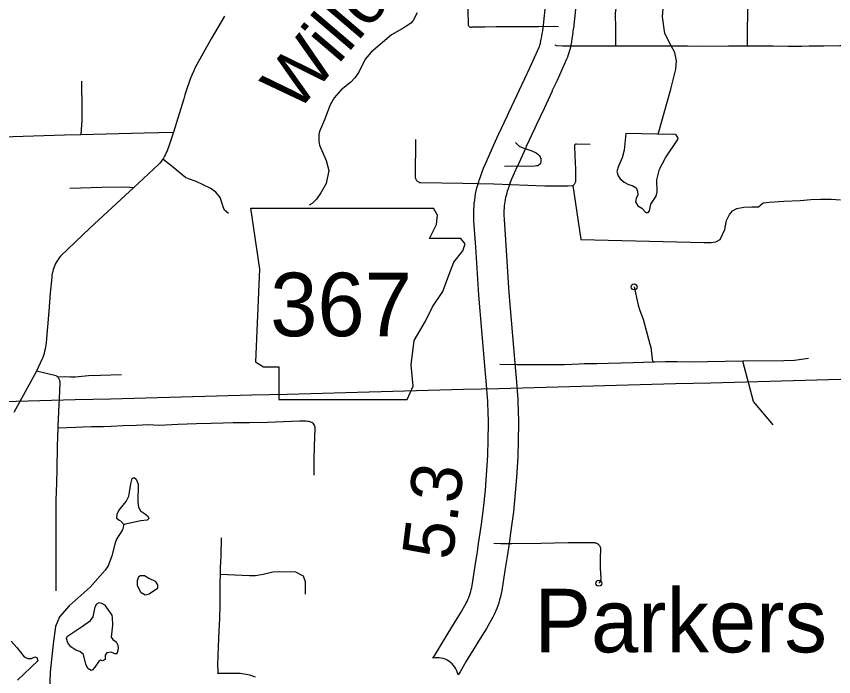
# Model space of a CAD drawing. Extents: x -19 to 366, y -4 to 359.
# Drawn here: x 152.307 to 153.594, y 182.486 to 183.524 of the extents above; entities that cross this region are included whole.
import ezdxf

# ---------------------------------------------------------------- set-up
doc = ezdxf.new("R2010")
doc.units = 0
for name, color, linetype in [('Level 10', 7, 'Continuous'), ('Level 21', 7, 'Continuous'), ('Level 24', 7, 'Continuous'), ('Level 31', 7, 'Continuous'), ('Level 32', 7, 'Continuous'), ('Level 35', 7, 'Continuous'), ('Level 48', 7, 'Continuous'), ('Level 60', 7, 'Continuous')]:
    doc.layers.add(name, color=color, linetype=linetype)

msp = doc.modelspace()

# ---------------------------------------------------------------- linework, layer by layer
at = {"layer": 'Level 10'}
for p, q in [((153.1844, 183.5056), (153.1843, 183.5052)), ((153.1792, 183.4741), (153.1791, 183.4735)), ((153.1507, 183.4066), (153.1508, 183.4067)), ((153.1235, 183.3485), (153.1236, 183.3485)), ((153.1093, 183.3177), (153.1093, 183.3177)), ((153.0504, 183.3025), (153.0499, 183.3015)), ((153.0937, 183.2834), (153.0933, 183.2825)), ((153.0817, 183.2533), (153.0816, 183.253)), ((153.0921, 182.9788), (153.0921, 182.9788)), ((153.0827, 182.6914), (153.0826, 182.6912))]:
    msp.add_line(p, q, dxfattribs=at)
for points in [[(153.1373, 183.5104), (153.1415, 183.5515), (153.1426, 183.5598), (153.1437, 183.5679), (153.145, 183.576), (153.1514, 183.6125), (153.1599, 183.6541), (153.1603, 183.6563)], [(153.2069, 183.6477), (153.2064, 183.645), (153.1979, 183.6037), (153.1917, 183.5682), (153.1905, 183.5609), (153.1895, 183.5535), (153.1886, 183.5462), (153.1844, 183.5056)], [(153.1329, 183.4839), (153.1338, 183.4885), (153.1347, 183.4929), (153.1355, 183.4973), (153.1361, 183.5018), (153.1368, 183.5062), (153.1373, 183.5109)], [(153.1843, 183.5052), (153.1837, 183.5001), (153.183, 183.4948), (153.1822, 183.4896), (153.1812, 183.4843), (153.1802, 183.4791), (153.1792, 183.4741)], [(153.1079, 183.4268), (153.1157, 183.4433), (153.1303, 183.4758), (153.1309, 183.4773), (153.1315, 183.4789), (153.132, 183.4807), (153.1325, 183.4823), (153.133, 183.4845)], [(153.1791, 183.4735), (153.1783, 183.4705), (153.1774, 183.4671), (153.1764, 183.4639), (153.1752, 183.4605), (153.1738, 183.4572), (153.1587, 183.4235), (153.1507, 183.4066)], [(153.0806, 183.3685), (153.0829, 183.3734), (153.0953, 183.3997), (153.1079, 183.4267)], [(153.1508, 183.4067), (153.1382, 183.3796), (153.1258, 183.3533), (153.1235, 183.3485)], [(153.0662, 183.3373), (153.0671, 183.3394), (153.0806, 183.3685)], [(153.1236, 183.3485), (153.1101, 183.3196), (153.1093, 183.3177)], [(153.0499, 183.3015), (153.0502, 183.3021), (153.0552, 183.3131), (153.0662, 183.3373)], [(153.1093, 183.3177), (153.0983, 183.2935), (153.0936, 183.2833), (153.0937, 183.2834)], [(153.0367, 183.2679), (153.0386, 183.2737), (153.0407, 183.2797), (153.043, 183.2856), (153.0454, 183.2914), (153.0479, 183.2972), (153.0504, 183.3025)], [(153.0933, 183.2825), (153.091, 183.2777), (153.089, 183.273), (153.087, 183.2681), (153.0851, 183.2633), (153.0834, 183.2584), (153.0817, 183.2533)], [(153.0449, 182.9748), (153.0356, 183.0859), (153.0308, 183.1611), (153.0279, 183.2027), (153.0277, 183.2114), (153.0277, 183.2161), (153.0278, 183.221), (153.028, 183.2258), (153.0284, 183.2306), (153.029, 183.2355), (153.0297, 183.2403), (153.0305, 183.2451), (153.0315, 183.2498), (153.0326, 183.2546), (153.0339, 183.2593), (153.0354, 183.264), (153.0368, 183.2682)], [(153.0816, 183.253), (153.0804, 183.2494), (153.0794, 183.2461), (153.0785, 183.2428), (153.0777, 183.2396), (153.077, 183.2362), (153.0764, 183.2328), (153.0759, 183.2294), (153.0755, 183.2261), (153.0753, 183.2226), (153.0751, 183.2192), (153.075, 183.2159), (153.0751, 183.2122), (153.0752, 183.2048), (153.0781, 183.1643), (153.0828, 183.0894), (153.0921, 182.9788)], [(153.0358, 182.6982), (153.0398, 182.7253), (153.0429, 182.7501), (153.0458, 182.7791), (153.0477, 182.8024), (153.0495, 182.8336), (153.0503, 182.8584), (153.0507, 182.8831), (153.0502, 182.9059), (153.0499, 182.9122), (153.0496, 182.9187), (153.0492, 182.9251), (153.0487, 182.9315), (153.0482, 182.938), (153.0475, 182.9447), (153.0449, 182.9747)], [(153.0921, 182.9788), (153.0947, 182.949), (153.0953, 182.9423), (153.0959, 182.9354), (153.0965, 182.9284), (153.0969, 182.9214), (153.0972, 182.9144), (153.0975, 182.9073), (153.098, 182.8832), (153.0976, 182.8573), (153.0968, 182.8315), (153.0949, 182.7991), (153.093, 182.7749), (153.09, 182.7448), (153.0867, 182.7189), (153.0827, 182.6914)], [(152.9632, 182.5144), (152.9659, 182.5185), (152.9754, 182.5342), (152.9874, 182.5537), (152.9974, 182.5703), (153.0067, 182.5855), (153.0156, 182.6012), (153.017, 182.6039), (153.0183, 182.6068), (153.0196, 182.6099), (153.0207, 182.613), (153.0218, 182.6161), (153.0227, 182.6193), (153.0236, 182.6226), (153.0243, 182.6256), (153.0249, 182.6288), (153.0297, 182.6601), (153.0333, 182.6822), (153.0358, 182.6985)], [(153.0826, 182.6912), (153.0801, 182.6748), (153.0765, 182.6527), (153.0716, 182.6208), (153.0707, 182.6161), (153.0696, 182.6111), (153.0683, 182.6065), (153.0669, 182.6018), (153.0653, 182.5971), (153.0637, 182.5927), (153.0618, 182.588), (153.0597, 182.5835), (153.0574, 182.5789), (153.0476, 182.5615), (153.0379, 182.5456), (153.0278, 182.529), (153.0158, 182.5096), (153.006, 182.4933), (153.0028, 182.4885)]]:
    msp.add_lwpolyline(points, dxfattribs=at)
msp.add_arc((152.9702, 182.4818), 0.0334, 11.6032, 102.0217, dxfattribs=at)
at = {"layer": 'Level 21'}
for p, q in [((152.6758, 183.2228), (152.6902, 183.1267)), ((152.9706, 183.2116), (152.9639, 183.2227)), ((152.969, 183.1972), (152.9706, 183.2116)), ((152.9578, 183.1747), (152.969, 183.1972)), ((153.0074, 183.1747), (152.9578, 183.1747)), ((153.0138, 183.1667), (153.0074, 183.1747)), ((153.0106, 183.1555), (153.0138, 183.1667)), ((152.9962, 183.1379), (153.0106, 183.1555)), ((152.6902, 183.1267), (152.6838, 182.9809)), ((152.9882, 183.1171), (152.9962, 183.1379)), ((152.9786, 183.0914), (152.9882, 183.1171)), ((152.9626, 183.0674), (152.9786, 183.0914)), ((152.9514, 183.045), (152.9626, 183.0674)), ((152.9337, 183.0145), (152.9514, 183.045)), ((152.9289, 182.9761), (152.9337, 183.0145)), ((152.6838, 182.9809), (152.6966, 182.9729)), ((152.6966, 182.9729), (152.7207, 182.9729)), ((152.7207, 182.9729), (152.7207, 182.9216)), ((152.9321, 182.9424), (152.9289, 182.9761)), ((152.9225, 182.9216), (152.9321, 182.9424)), ((152.7207, 182.9216), (152.9225, 182.9216))]:
    msp.add_line(p, q, dxfattribs=at)
msp.add_lwpolyline([(152.6758, 183.2228), (152.9639, 183.2227)], dxfattribs=at)
at = {"layer": 'Level 31'}
msp.add_line((153.4585, 183.4775), (153.4594, 183.6425), dxfattribs=at)
for points in [[(153.2673, 183.6398), (153.2537, 183.5558), (153.2504, 183.5296), (153.2509, 183.5042), (153.2509, 183.4775)], [(153.1608, 183.508), (153.1551, 183.5084), (153.1294, 183.5078), (153.1112, 183.5081), (153.1016, 183.5079), (153.0628, 183.5079), (153.0448, 183.5073), (153.0243, 183.5073), (153.0235, 183.5072), (153.0228, 183.5072), (153.0221, 183.5074), (153.0214, 183.5077), (153.0208, 183.5081), (153.0202, 183.5086), (153.0198, 183.5092), (153.0195, 183.5099), (153.0193, 183.5106), (153.0192, 183.5113), (153.019, 183.5343), (153.0189, 183.5679)], [(152.6352, 183.5248), (152.6139, 183.4893), (152.5886, 183.4438), (152.586, 183.4378), (152.5834, 183.4318), (152.581, 183.4258), (152.5787, 183.4196), (152.5766, 183.4135), (152.5745, 183.4073), (152.5726, 183.401), (152.5708, 183.3947), (152.5546, 183.342)], [(153.2509, 183.4775), (153.2301, 183.4775), (153.1914, 183.4776), (153.1671, 183.4778), (153.1579, 183.4781), (153.156, 183.479)], [(153.4567, 183.4775), (153.4482, 183.4774), (153.4286, 183.4774), (153.3865, 183.4773), (153.3643, 183.4774), (153.3358, 183.4777), (153.3225, 183.4776), (153.2509, 183.4775)], [(153.4585, 183.4775), (153.4567, 183.4775)], [(153.6393, 183.4783), (153.6235, 183.478), (153.6038, 183.478), (153.5788, 183.4777), (153.5557, 183.4775), (153.5442, 183.4773), (153.5225, 183.4773), (153.4992, 183.4775), (153.476, 183.4774), (153.4593, 183.4775), (153.4585, 183.4775)], [(152.4097, 183.4225), (152.4097, 183.4152), (152.4106, 183.3853), (152.4102, 183.361), (152.4088, 183.3388)], [(152.128, 183.335), (152.1293, 183.3343), (152.1307, 183.3337), (152.1321, 183.3332), (152.1335, 183.3328), (152.135, 183.3325), (152.1364, 183.3323), (152.1379, 183.3322), (152.1394, 183.3322), (152.1409, 183.3324), (152.1614, 183.3328), (152.1884, 183.3333), (152.2111, 183.3338), (152.2283, 183.3335), (152.302, 183.3356), (152.3833, 183.3381), (152.4088, 183.3388)], [(152.4088, 183.3388), (152.5087, 183.3412), (152.5546, 183.342)], [(152.5546, 183.342), (152.5468, 183.3189), (152.5458, 183.3159), (152.5446, 183.3129), (152.5433, 183.31), (152.5419, 183.3071), (152.5404, 183.3043), (152.5388, 183.3015), (152.5377, 183.2997)], [(153.0592, 183.2606), (153.0106, 183.2617), (152.9438, 183.2625), (152.9428, 183.2627), (152.9419, 183.263), (152.941, 183.2634), (152.9401, 183.2639), (152.9393, 183.2645), (152.9385, 183.2652), (152.9379, 183.2659), (152.9373, 183.2667), (152.9368, 183.2676), (152.9364, 183.2686), (152.9362, 183.2695), (152.936, 183.2705), (152.936, 183.2715), (152.936, 183.2725), (152.9362, 183.3309)], [(153.0933, 183.3259), (153.0993, 183.3203), (153.1065, 183.3169), (153.1191, 183.3129), (153.1258, 183.3099), (153.1287, 183.3078), (153.1308, 183.3057), (153.1322, 183.3034), (153.1331, 183.3006), (153.1334, 183.2981), (153.1333, 183.2963), (153.1324, 183.2934), (153.1312, 183.2916), (153.1302, 183.2906), (153.1284, 183.2895), (153.1263, 183.2892), (153.1235, 183.289), (153.0761, 183.2881)], [(153.2106, 183.3228), (153.1893, 183.3235), (153.1887, 183.3236), (153.1881, 183.3234), (153.1875, 183.3232), (153.187, 183.3228), (153.1866, 183.3223), (153.1863, 183.3218), (153.1861, 183.3211), (153.1861, 183.3205), (153.1867, 183.3052), (153.1877, 183.2841), (153.1878, 183.268), (153.1879, 183.2668), (153.1879, 183.2656), (153.1877, 183.2644), (153.1874, 183.2633), (153.1869, 183.2622), (153.1864, 183.2611), (153.1857, 183.2601), (153.1849, 183.2592), (153.184, 183.2585), (153.1834, 183.2581)], [(152.5377, 183.2997), (152.5371, 183.2988), (152.5353, 183.2962), (152.5334, 183.2936), (152.5313, 183.2912), (152.4917, 183.2544)], [(152.6411, 183.2143), (152.6351, 183.2197), (152.6329, 183.2246), (152.6316, 183.2302), (152.628, 183.2396), (152.6215, 183.2477), (152.6126, 183.2539), (152.5902, 183.2645), (152.5782, 183.269), (152.5734, 183.271), (152.5501, 183.2904), (152.5377, 183.2997)], [(152.4917, 183.2544), (152.4794, 183.243), (152.4228, 183.191), (152.3766, 183.1469), (152.3747, 183.1445), (152.373, 183.1421), (152.3714, 183.1396), (152.3699, 183.137), (152.3685, 183.1343), (152.3673, 183.1316), (152.3662, 183.1288), (152.3653, 183.1259), (152.3645, 183.123), (152.3638, 183.1201), (152.3633, 183.1171), (152.3629, 183.1142), (152.3606, 183.0888), (152.3584, 183.0606), (152.3541, 183.0113), (152.3537, 183.0078), (152.3532, 183.0044), (152.3526, 183.001), (152.3518, 182.9976), (152.3509, 182.9942), (152.3499, 182.9909), (152.3488, 182.9876), (152.3475, 182.9844), (152.3391, 182.966)], [(152.4917, 183.2544), (152.4862, 183.2553), (152.4748, 183.2557), (152.442, 183.255), (152.3915, 183.2534)], [(153.1834, 183.2581), (153.183, 183.2578), (153.1756, 183.2574), (153.1583, 183.2572), (153.1393, 183.2575), (153.0592, 183.2606)], [(153.1834, 183.2581), (153.1964, 183.1733), (153.3904, 183.1687), (153.4012, 183.1687), (153.4086, 183.1699), (153.4156, 183.1735), (153.4228, 183.1891), (153.4257, 183.2035), (153.43, 183.2129), (153.4348, 183.2184), (153.442, 183.2222), (153.4528, 183.2244), (153.4653, 183.2246), (153.4757, 183.2246), (153.4833, 183.2309), (153.4925, 183.2323)], [(153.4925, 183.2323), (153.5159, 183.2338), (153.5417, 183.2345), (153.5584, 183.2363), (153.5742, 183.2369), (153.5905, 183.2366), (153.6052, 183.236)], [(153.2801, 183.0988), (153.2815, 183.0923), (153.2842, 183.0795), (153.2863, 183.0698), (153.2891, 183.0615), (153.2942, 183.0478), (153.3048, 183.0088), (153.3062, 183.0037), (153.3087, 182.985), (153.3093, 182.9802)], [(153.3093, 182.9802), (153.295, 182.9796), (153.2788, 182.9792), (153.2597, 182.9788), (153.2394, 182.9784), (153.2215, 182.9778), (153.2043, 182.9775), (153.2012, 182.9775), (153.1935, 182.9772), (153.1706, 182.9763), (153.1573, 182.9764), (153.1439, 182.9764), (153.1335, 182.9764), (153.1138, 182.9764), (153.0956, 182.9764), (153.0685, 182.9768)], [(153.451, 182.9818), (153.3679, 182.9805), (153.348, 182.9809), (153.3297, 182.9807), (153.3127, 182.9803), (153.3093, 182.9802)], [(152.3391, 182.966), (152.3032, 182.9014)], [(152.3727, 182.9566), (152.3725, 182.9569), (152.3716, 182.9577), (152.3707, 182.9584), (152.3698, 182.959), (152.3391, 182.966)], [(152.3727, 182.9566), (152.3732, 182.9561), (152.3738, 182.9552), (152.3744, 182.9542), (152.3749, 182.9532), (152.3752, 182.9521), (152.3754, 182.951), (152.3756, 182.9499), (152.3756, 182.9488), (152.3755, 182.9476), (152.3746, 182.9234), (152.3734, 182.9028), (152.3725, 182.8789), (152.3724, 182.8765)], [(152.7741, 182.8841), (152.7728, 182.8852), (152.7712, 182.8861), (152.7696, 182.8867), (152.7679, 182.887), (152.7661, 182.8871), (152.7629, 182.8873), (152.7555, 182.8874), (152.7533, 182.8874), (152.7025, 182.8852), (152.6743, 182.885), (152.6596, 182.8848), (152.6489, 182.8847), (152.6328, 182.8844), (152.6143, 182.8839), (152.591, 182.8834), (152.5616, 182.8823), (152.5328, 182.8809), (152.5146, 182.8815), (152.4958, 182.8806), (152.475, 182.8803), (152.4567, 182.879), (152.4444, 182.8787), (152.4256, 182.8786), (152.4122, 182.8783), (152.4009, 182.8773), (152.3724, 182.8765)], [(152.7741, 182.8841), (152.7753, 182.8828), (152.7762, 182.8813), (152.7769, 182.8798), (152.7773, 182.8781), (152.7775, 182.8763), (152.7761, 182.848), (152.7757, 182.8265), (152.7758, 182.8025)], [(152.3724, 182.8765), (152.3714, 182.848), (152.3709, 182.8116), (152.3703, 182.7905), (152.3694, 182.763), (152.3693, 182.7435), (152.3693, 182.7162), (152.3696, 182.6206)], [(152.6299, 182.7041), (152.6291, 182.6752), (152.6284, 182.6571), (152.6276, 182.6226), (152.6275, 182.5986), (152.627, 182.5771), (152.626, 182.5576), (152.625, 182.5329), (152.624, 182.5037), (152.6246, 182.4959), (152.6246, 182.4909)], [(153.2245, 182.6325), (153.2254, 182.6334), (153.2263, 182.6343), (153.227, 182.6355), (153.2276, 182.6367), (153.2279, 182.638), (153.2281, 182.6392), (153.2281, 182.6406), (153.2273, 182.6563), (153.2271, 182.6708), (153.2274, 182.6876), (153.227, 182.6889), (153.2264, 182.6901), (153.2257, 182.6913), (153.2248, 182.6924), (153.2238, 182.6933), (153.2227, 182.6941), (153.2215, 182.6948), (153.2202, 182.6953), (153.2188, 182.6957), (153.2175, 182.6958), (153.1981, 182.6961), (153.176, 182.6958), (153.1549, 182.6954), (153.1334, 182.6951), (153.0874, 182.6943), (153.0703, 182.6943), (153.0592, 182.6948)], [(152.6838, 182.4845), (152.6809, 182.4856), (152.678, 182.4867), (152.675, 182.4876), (152.672, 182.4884), (152.669, 182.4891), (152.6659, 182.4896), (152.6628, 182.49), (152.6598, 182.4903), (152.6567, 182.4904), (152.6246, 182.4907), (152.6246, 182.4909)]]:
    msp.add_lwpolyline(points, dxfattribs=at)
for centre in [(153.2801, 183.0988), (153.2245, 182.6325)]:
    msp.add_circle(centre, 0.00473, dxfattribs=at)
at = {"layer": 'Level 32'}
for points in [[(153.5548, 182.9863), (153.5328, 182.9828), (153.5158, 182.9823), (153.451, 182.9818)], [(153.4992, 182.8816), (153.4681, 182.9186), (153.451, 182.9818)], [(152.4728, 182.9606), (152.4398, 182.9593), (152.4211, 182.9589), (152.4103, 182.958), (152.3997, 182.9566), (152.3928, 182.9567), (152.3835, 182.9575), (152.3727, 182.9566)], [(152.6281, 182.6466), (152.6746, 182.6446), (152.6839, 182.6446), (152.6958, 182.6466), (152.711, 182.6506), (152.7216, 182.6512), (152.7468, 182.6506), (152.7587, 182.6439), (152.762, 182.6353), (152.762, 182.6247), (152.762, 182.6155)]]:
    msp.add_lwpolyline(points, dxfattribs=at)
at = {"layer": 'Level 35'}
for points in [[(153.3179, 183.339), (153.3381, 183.41), (153.346, 183.4415), (153.3469, 183.4546), (153.3443, 183.4678), (153.3381, 183.4791), (153.3285, 183.4975), (153.325, 183.5238), (153.3294, 183.5816)], [(152.9385, 183.5298), (152.9323, 183.518), (152.9287, 183.5138), (152.9172, 183.5065), (152.8979, 183.4956), (152.8661, 183.4683), (152.8563, 183.4572), (152.8468, 183.4367), (152.8403, 183.4275), (152.8341, 183.4207), (152.819, 183.4088), (152.8077, 183.3962), (152.8015, 183.3852), (152.7927, 183.3618), (152.7844, 183.3432), (152.7835, 183.3386), (152.7835, 183.328), (152.7848, 183.3219), (152.7952, 183.2975), (152.7992, 183.2817), (152.7949, 183.2616), (152.7868, 183.2466), (152.78, 183.2367), (152.7731, 183.2298), (152.7686, 183.2272)], [(153.2671, 183.3399), (153.2646, 183.3137), (153.2614, 183.3021), (153.2554, 183.2886), (153.2531, 183.2801), (153.2547, 183.2736), (153.2583, 183.2689), (153.2644, 183.2634), (153.271, 183.26), (153.2771, 183.2583), (153.2833, 183.2546), (153.2854, 183.2495), (153.2857, 183.2438), (153.2834, 183.2379), (153.2825, 183.2326), (153.2857, 183.2263), (153.2922, 183.2226), (153.2985, 183.2161), (153.3021, 183.2158), (153.3045, 183.2186), (153.3062, 183.2287), (153.315, 183.2418), (153.3161, 183.2481), (153.3157, 183.2675), (153.32, 183.284), (153.3296, 183.3017), (153.349, 183.3308), (153.3494, 183.3329), (153.3461, 183.3382), (153.3435, 183.339), (153.3406, 183.3386)], [(153.3406, 183.3386), (153.2671, 183.3399)], [(152.4765, 182.725), (152.4717, 182.73), (152.4692, 182.7311), (152.4655, 182.7342), (152.4662, 182.7411), (152.4687, 182.7468), (152.48, 182.7609), (152.4845, 182.7695), (152.4857, 182.7758), (152.4878, 182.7891), (152.4895, 182.7975), (152.4927, 182.7987), (152.496, 182.7961), (152.4989, 182.7884), (152.4984, 182.7603), (152.4998, 182.7522), (152.5026, 182.7465), (152.5105, 182.741), (152.5145, 182.7382), (152.5159, 182.7343), (152.5131, 182.7317), (152.5033, 182.7308), (152.4765, 182.725)], [(152.4765, 182.725), (152.4744, 182.7166), (152.465, 182.7016), (152.4627, 182.696), (152.4576, 182.6755), (152.4518, 182.6598), (152.4474, 182.6531), (152.4237, 182.6264), (152.3906, 182.5969), (152.3754, 182.5794), (152.369, 182.5645), (152.3652, 182.5372), (152.3606, 182.4926), (152.3595, 182.4614), (152.35, 182.3855), (152.3448, 182.3666), (152.3366, 182.3505), (152.3351, 182.3412), (152.3352, 182.327), (152.3317, 182.2943), (152.3318, 182.2855), (152.3266, 182.2704), (152.3143, 182.2436), (152.2985, 182.2183)], [(152.5165, 182.6155), (152.5103, 182.6135), (152.5038, 182.6173), (152.4979, 182.6286), (152.4983, 182.6369), (152.5004, 182.6431), (152.5027, 182.6446), (152.5089, 182.6444), (152.5158, 182.6403)], [(152.5158, 182.6403), (152.5258, 182.6356), (152.5295, 182.6301), (152.5294, 182.6241), (152.5165, 182.6155)], [(152.4113, 182.5647), (152.4239, 182.574), (152.428, 182.5798), (152.4315, 182.5954), (152.4342, 182.5999), (152.4378, 182.602), (152.4414, 182.6013), (152.4462, 182.5984), (152.4575, 182.5821), (152.4583, 182.5779), (152.4589, 182.5665), (152.4566, 182.5477), (152.459, 182.544), (152.4644, 182.5403), (152.4671, 182.5348), (152.4678, 182.5303), (152.4662, 182.5227)], [(152.4662, 182.5227), (152.4638, 182.5209), (152.4565, 182.5242), (152.4497, 182.5231), (152.4474, 182.5191), (152.4469, 182.5126), (152.4428, 182.5104), (152.4397, 182.5113), (152.4364, 182.509), (152.4311, 182.5004), (152.4273, 182.4963), (152.4253, 182.4953), (152.4201, 182.4981), (152.4168, 182.505), (152.4129, 182.5205), (152.4073, 182.5251), (152.4012, 182.5271), (152.3931, 182.5325), (152.3881, 182.5388), (152.3864, 182.5456), (152.3877, 182.5494), (152.4113, 182.5647)], [(152.2992, 182.5415), (152.3081, 182.5316), (152.3196, 182.5166), (152.3255, 182.5139), (152.331, 182.5142), (152.3365, 182.5168), (152.3397, 182.5155), (152.3409, 182.5106)], [(152.3409, 182.5106), (152.3093, 182.4798)]]:
    msp.add_lwpolyline(points, dxfattribs=at)
at = {"layer": 'Level 60'}
for points in [[(154.1159, 1.8709), (153.9063, 10.4874), (153.696, 19.1041), (153.485, 27.7209), (153.2733, 36.3378), (153.0608, 44.9549), (152.8476, 53.5721), (152.6337, 62.1894), (152.419, 70.8069), (152.2036, 79.4245), (151.9875, 88.0422), (151.7707, 96.6601), (151.5531, 105.2782), (151.3348, 113.8963), (151.1158, 122.5147), (150.8961, 131.1331), (150.6757, 139.7517), (150.4545, 148.3704), (150.2326, 156.9893), (150.0101, 165.6083), (149.7867, 174.2275), (149.5627, 182.8468), (149.338, 191.4662), (149.1125, 200.0858), (148.8864, 208.7055), (148.6595, 217.3254), (148.4319, 225.9454), (148.2037, 234.5655), (147.9747, 243.1858), (147.745, 251.8063), (147.5146, 260.4269), (147.2835, 269.0476), (147.0517, 277.6685), (146.8191, 286.2895), (146.5859, 294.9106), (146.352, 303.5319), (146.1174, 312.1534), (145.8821, 320.775), (145.6461, 329.3967), (145.4094, 338.0186), (145.172, 346.6406)], [(0, 180.8999), (7.1228, 180.9044), (14.2457, 180.9176), (21.3685, 180.9397), (28.4912, 180.9706), (35.614, 181.0103), (42.7366, 181.0589), (49.8592, 181.1163), (56.9818, 181.1825), (64.1042, 181.2575), (71.2266, 181.3414), (78.3488, 181.4341), (85.4709, 181.5357), (92.5929, 181.646), (99.7147, 181.7652), (106.8364, 181.8933), (113.9579, 182.0301), (121.0793, 182.1758), (128.2005, 182.3303), (135.3214, 182.4936), (142.4422, 182.6658), (149.5627, 182.8468), (156.683, 183.0366), (163.8031, 183.2352), (170.9229, 183.4427), (178.0425, 183.659), (185.1617, 183.8841), (192.2807, 184.1181), (199.3994, 184.3608), (206.5178, 184.6124), (213.6359, 184.8728), (220.7537, 185.1421), (227.8711, 185.4201), (234.9881, 185.707), (242.1048, 186.0027), (249.2212, 186.3073), (256.3371, 186.6206), (263.4526, 186.9428), (270.5678, 187.2738), (277.6825, 187.6136), (284.7968, 187.9622), (291.9107, 188.3197), (299.0241, 188.6859), (306.1371, 189.061), (313.2495, 189.4449), (320.3615, 189.8377), (327.4731, 190.2392), (334.5841, 190.6495), (341.6946, 191.0687)]]:
    msp.add_spline(points, degree=3, dxfattribs=at)

# ---------------------------------------------------------------- texts
at = {"layer": 'Level 21'}
msp.add_text('367', height=0.1, dxfattribs=at).set_placement((152.707, 183.0211))
at = {"layer": 'Level 24'}
msp.add_text('Parkers', height=0.1, dxfattribs=at).set_placement((153.123, 182.5237))
at = {"layer": 'Level 35'}
msp.add_text('Willow', height=0.08, rotation=49.57, dxfattribs=at).set_placement((152.7486, 183.3712))
at = {"layer": 'Level 48'}
msp.add_text('5.3', height=0.08, rotation=82.822, dxfattribs=at).set_placement((152.9937, 182.6674))

doc.saveas('drawing.dxf')
